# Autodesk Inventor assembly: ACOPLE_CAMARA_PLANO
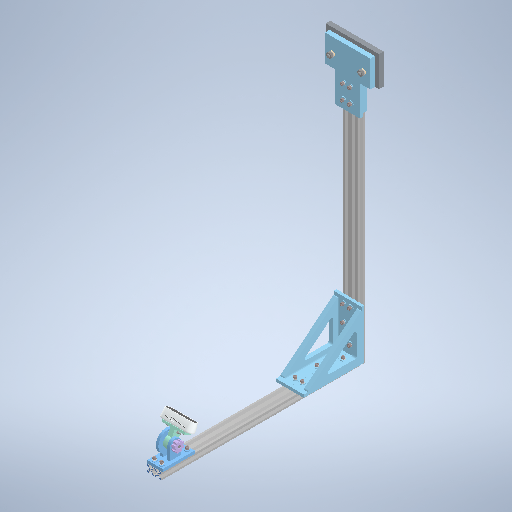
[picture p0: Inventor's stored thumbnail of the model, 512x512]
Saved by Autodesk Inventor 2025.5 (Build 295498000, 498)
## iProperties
Company: Open CASCADE
Created: 2026-10
Part Number: ACOPLE_CAMARA_PLANO
Description: Open CASCADE Model
Document SubType Name: Assembly
Designer: Luis M
Authority: Unknown
Sending System: Open CASCADE 7.9
Preprocessor: Open CASCADE STEP processor 7.9
Title: Open CASCADE Shape Model
Author: Author
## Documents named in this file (26)
- C:\Users\Luis M\Desktop\TESIS\CAD_TESIS\ACOPLE_CAMARA\ACOPLE_CAMARA_PLANO.iam
- C:\Users\Luis M\Desktop\TESIS\CAD_TESIS\ACOPLE_CAMARA\BOM_PLANO\IPT\ACAM-P02.ipt
- C:\Users\Luis M\Desktop\TESIS\CAD_TESIS\ACOPLE_CAMARA\BOM_PLANO\IPT\ACAM-P03.ipt
- C:\Users\Luis M\Desktop\TESIS\CAD_TESIS\ACOPLE_CAMARA\BOM_PLANO\IPT\ACAM-REF01.ipt
- C:\Users\Luis M\Desktop\TESIS\CAD_TESIS\ACOPLE_CAMARA\BOM_PLANO\IPT\ACAM-P08_izq.ipt
- C:\Users\Luis M\Desktop\TESIS\CAD_TESIS\ACOPLE_CAMARA\BOM_PLANO\IPT\ACAM-P08_der.ipt
- C:\Users\Luis M\Desktop\TESIS\CAD_TESIS\ACOPLE_CAMARA\BOM_PLANO\IPT\ACAM-C15.ipt
- C:\Users\Luis M\Desktop\TESIS\CAD_TESIS\ACOPLE_CAMARA\BOM_PLANO\IPT\ACAM-C01.ipt
- C:\Users\Luis M\Desktop\TESIS\CAD_TESIS\ACOPLE_CAMARA\BOM_PLANO\IPT\ACAM-C02.ipt
- C:\Users\Luis M\Desktop\TESIS\CAD_TESIS\ACOPLE_CAMARA\BOM_PLANO\IPT\ACAM-C03.ipt
- C:\Users\Luis M\Desktop\TESIS\CAD_TESIS\ACOPLE_CAMARA\BOM_PLANO\IPT\ACAM-C06.ipt
- C:\Users\Luis M\Desktop\TESIS\CAD_TESIS\ACOPLE_CAMARA\BOM_PLANO\IPT\ACAM-C04.ipt
- C:\Users\Luis M\Desktop\TESIS\CAD_TESIS\ACOPLE_CAMARA\BOM_PLANO\IPT\ACAM-C08.ipt
- C:\Users\Luis M\Desktop\TESIS\CAD_TESIS\ACOPLE_CAMARA\BOM_PLANO\IPT\ACAM-C09.ipt
- C:\Users\Luis M\Desktop\TESIS\CAD_TESIS\ACOPLE_CAMARA\BOM_PLANO\IPT\ACAM-C05.ipt
- C:\Users\Luis M\Desktop\TESIS\CAD_TESIS\ACOPLE_CAMARA\BOM_PLANO\IPT\ACAM-C07.ipt
- C:\Users\Luis M\Desktop\TESIS\CAD_TESIS\ACOPLE_CAMARA\BOM_PLANO\IPT\ACAM-C10.ipt
- C:\Users\Luis M\Desktop\TESIS\CAD_TESIS\ACOPLE_CAMARA\BOM_PLANO\IPT\ACAM-C11.ipt
- C:\Users\Luis M\Desktop\TESIS\CAD_TESIS\ACOPLE_CAMARA\BOM_PLANO\IPT\ACAM-C12.ipt
- C:\Users\Luis M\Desktop\TESIS\CAD_TESIS\ACOPLE_CAMARA\BOM_PLANO\IPT\ACAM-C13.ipt
- C:\Users\Luis M\Desktop\TESIS\CAD_TESIS\ACOPLE_CAMARA\BOM_PLANO\IPT\ACAM-C14.ipt
- C:\Users\Luis M\Desktop\TESIS\CAD_TESIS\ACOPLE_CAMARA\BOM_PLANO\IPT\ACAM-P01.ipt
- C:\Users\Luis M\Desktop\TESIS\CAD_TESIS\ACOPLE_CAMARA\BOM_PLANO\IPT\ACAM-P04.ipt
- C:\Users\Luis M\Desktop\TESIS\CAD_TESIS\ACOPLE_CAMARA\BOM_PLANO\IPT\ACAM-P05.ipt
- C:\Users\Luis M\Desktop\TESIS\CAD_TESIS\ACOPLE_CAMARA\BOM_PLANO\IPT\ACAM-P06.ipt
- C:\Users\Luis M\Desktop\TESIS\CAD_TESIS\ACOPLE_CAMARA\BOM_PLANO\IPT\ACAM-P07.ipt
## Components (94 placed, 24 different names)
1. ACAM-C01 Perfil V-Slot 2040 × 700:1 — Coincidencia:26, Nivelación:1, Nivelación:2, Coincidencia:36, Coincidencia:37, Coincidencia:38, Coincidencia:47, UF_01_Plano_1, UF_01_Plano_2, UF_01_Plano_3, UF_02_Plano_1, UF_02_Plano_2, UF_02_Plano_3, UF_03_Plano_1, UF_03_Plano_2, UF_03_Plano_3, UF_04_Plano_1, UF_04_Plano_2, UF_04_Plano_3, UF_05_Plano_1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
2. ACAM-C02 Perfil V-Slot 2040 × 550:1 — Coincidencia:26, Nivelación:1, Nivelación:2, Coincidencia:27, Coincidencia:28, Coincidencia:29, Coincidencia:46
3. ACAM-P01 Horquilla de cámara:1 — CM_01_Plano_1, CM_01_Plano_2, CM_01_Plano_3
4. ACAM-P02 Placa portacámara:1 — CM_02_Plano_1, CM_02_Plano_2, CM_02_Plano_3
5. ACAM-P03 Pomo de ajuste M5:1 — CM_03_Plano_1, CM_03_Plano_2, CM_03_Plano_3
6. ACAM-P04 Adaptador Jaco2–2040:1 — UF_01_Plano_1, UF_01_Plano_2, UF_01_Plano_3
7. ACAM-REF01 Base Jaco2 — referencia:1 — UF_02_Plano_1, UF_02_Plano_2, UF_02_Plano_3
8. ACAM-C03 Tornillo Allen M5×40:1 — CM_04_Plano_1, CM_04_Plano_2, CM_04_Plano_3
9. ACAM-C06 Arandela de presión M5 — DIN 127 B:1 — CM_05_Plano_1, CM_05_Plano_2, CM_05_Plano_3
10. ACAM-C06 Arandela de presión M5 — DIN 127 B:2 — CM_06_Plano_1, CM_06_Plano_2, CM_06_Plano_3
11. ACAM-C04 Tuerca hexagonal M5:1 — CM_07_Plano_1, CM_07_Plano_2, CM_07_Plano_3
12. ACAM-C08 Tornillo Allen M3×8:1 — CM_08_Plano_1, CM_08_Plano_2, CM_08_Plano_3
13. ACAM-C09 Arandela de presión M3 — DIN 127 B:1 — CM_09_Plano_1, CM_09_Plano_2, CM_09_Plano_3
14. ACAM-C08 Tornillo Allen M3×8:2 — CM_10_Plano_1, CM_10_Plano_2, CM_10_Plano_3
15. ACAM-C09 Arandela de presión M3 — DIN 127 B:2 — CM_11_Plano_1, CM_11_Plano_2, CM_11_Plano_3
16. ACAM-C05 Tornillo Allen M5×16:1 — CM_12_Plano_1, CM_12_Plano_2, CM_12_Plano_3
17. ACAM-C06 Arandela de presión M5 — DIN 127 B:3 — CM_13_Plano_1, CM_13_Plano_2, CM_13_Plano_3
18. ACAM-C07 Tuerca T M5 — modelo 2020:1 — CM_14_Plano_1, CM_14_Plano_2, CM_14_Plano_3
19. ACAM-C05 Tornillo Allen M5×16:2 — CM_15_Plano_1, CM_15_Plano_2, CM_15_Plano_3
20. ACAM-C06 Arandela de presión M5 — DIN 127 B:4 — CM_16_Plano_1, CM_16_Plano_2, CM_16_Plano_3
21. ACAM-C07 Tuerca T M5 — modelo 2020:2 — CM_17_Plano_1, CM_17_Plano_2, CM_17_Plano_3
22. ACAM-C05 Tornillo Allen M5×16:3 — UF_03_Plano_1, UF_03_Plano_2, UF_03_Plano_3
23. ACAM-C06 Arandela de presión M5 — DIN 127 B:5 — UF_04_Plano_1, UF_04_Plano_2, UF_04_Plano_3
24. ACAM-C07 Tuerca T M5 — modelo 2020:3 — UF_05_Plano_1, UF_05_Plano_2, UF_05_Plano_3
25. ACAM-C05 Tornillo Allen M5×16:4 — UF_06_Plano_1, UF_06_Plano_2, UF_06_Plano_3
26. ACAM-C06 Arandela de presión M5 — DIN 127 B:6 — UF_07_Plano_1, UF_07_Plano_2, UF_07_Plano_3
27. ACAM-C07 Tuerca T M5 — modelo 2020:4 — UF_08_Plano_1, UF_08_Plano_2, UF_08_Plano_3
28. ACAM-C05 Tornillo Allen M5×16:5 — CM_18_Plano_1, CM_18_Plano_2, CM_18_Plano_3
29. ACAM-C06 Arandela de presión M5 — DIN 127 B:7 — CM_19_Plano_1, CM_19_Plano_2, CM_19_Plano_3
30. ACAM-C07 Tuerca T M5 — modelo 2020:5 — CM_20_Plano_1, CM_20_Plano_2, CM_20_Plano_3
31. ACAM-C05 Tornillo Allen M5×16:6 — CM_21_Plano_1, CM_21_Plano_2, CM_21_Plano_3
32. ACAM-C06 Arandela de presión M5 — DIN 127 B:8 — CM_22_Plano_1, CM_22_Plano_2, CM_22_Plano_3
33. ACAM-C07 Tuerca T M5 — modelo 2020:6 — CM_23_Plano_1, CM_23_Plano_2, CM_23_Plano_3
34. ACAM-C05 Tornillo Allen M5×16:7 — UF_09_Plano_1, UF_09_Plano_2, UF_09_Plano_3
35. ACAM-C06 Arandela de presión M5 — DIN 127 B:9 — UF_10_Plano_1, UF_10_Plano_2, UF_10_Plano_3
36. ACAM-C07 Tuerca T M5 — modelo 2020:7 — UF_11_Plano_1, UF_11_Plano_2, UF_11_Plano_3
37. ACAM-C05 Tornillo Allen M5×16:8 — UF_12_Plano_1, UF_12_Plano_2, UF_12_Plano_3
38. ACAM-C06 Arandela de presión M5 — DIN 127 B:10 — UF_13_Plano_1, UF_13_Plano_2, UF_13_Plano_3
39. ACAM-C07 Tuerca T M5 — modelo 2020:8 — UF_14_Plano_1, UF_14_Plano_2, UF_14_Plano_3
40. ACAM-P05 Cartabón derecho:1
41. ACAM-P06 Cartabón izquierdo:1
42. ACAM-C05 Tornillo Allen M5×16:9 — Coincidencia:6, Coincidencia:12, Coincidencia:31, Coincidencia:54
43. ACAM-C06 Arandela de presión M5 — DIN 127 B:11 — Coincidencia:6, Coincidencia:12, Nivelación:23, Nivelación:25
44. ACAM-C07 Tuerca T M5 — modelo 2020:9 — Nivelación:3, Nivelación:8, Coincidencia:33
45. ACAM-C05 Tornillo Allen M5×16:10 — Coincidencia:4, Coincidencia:10, Coincidencia:34, Coincidencia:49
46. ACAM-C06 Arandela de presión M5 — DIN 127 B:12 — Coincidencia:4, Coincidencia:10, Nivelación:25, Nivelación:26, Coincidencia:48
47. ACAM-C07 Tuerca T M5 — modelo 2020:10 — Nivelación:5, Nivelación:6, Nivelación:10, Coincidencia:32
48. ACAM-C05 Tornillo Allen M5×16:11 — Coincidencia:3, Coincidencia:8, Coincidencia:35, Coincidencia:51
49. ACAM-C06 Arandela de presión M5 — DIN 127 B:13 — Coincidencia:3, Coincidencia:8, Nivelación:23, Nivelación:24
50. ACAM-C07 Tuerca T M5 — modelo 2020:11 — Nivelación:7, Nivelación:9, Coincidencia:34
51. ACAM-C05 Tornillo Allen M5×16:12 — Coincidencia:15, Coincidencia:25, Coincidencia:39, Coincidencia:56
52. ACAM-C06 Arandela de presión M5 — DIN 127 B:14 — Coincidencia:15, Coincidencia:25, Nivelación:31
53. ACAM-C07 Tuerca T M5 — modelo 2020:12 — Nivelación:12, Ángulo:5, Nivelación:17, Coincidencia:38, Coincidencia:40
54. ACAM-C05 Tornillo Allen M5×16:13 — Coincidencia:17, Coincidencia:23, Coincidencia:42, Coincidencia:60
55. ACAM-C06 Arandela de presión M5 — DIN 127 B:15 — Coincidencia:17, Coincidencia:23, Nivelación:28, Nivelación:29, Nivelación:32
56. ACAM-C07 Tuerca T M5 — modelo 2020:13 — Nivelación:16, Ángulo:4, Ángulo:5, Nivelación:17, Nivelación:18, Coincidencia:42
57. ACAM-C05 Tornillo Allen M5×16:14 — Coincidencia:19, Coincidencia:21, Coincidencia:44
58. ACAM-C06 Arandela de presión M5 — DIN 127 B:16 — Coincidencia:19, Coincidencia:21, Nivelación:28
59. ACAM-C07 Tuerca T M5 — modelo 2020:14 — Nivelación:15, Nivelación:16, Ángulo:3, Ángulo:4, Nivelación:18, Coincidencia:44, Coincidencia:59
60. ACAM-C05 Tornillo Allen M5×16:15 — Coincidencia:7, Coincidencia:13, Coincidencia:32, Coincidencia:53
61. ACAM-C06 Arandela de presión M5 — DIN 127 B:17 — Coincidencia:7, Coincidencia:13, Nivelación:26, Nivelación:27
62. ACAM-C07 Tuerca T M5 — modelo 2020:15 — Nivelación:3, Nivelación:4, Nivelación:8, Nivelación:9, Coincidencia:29, Coincidencia:35
63. ACAM-C05 Tornillo Allen M5×16:16 — Coincidencia:5, Coincidencia:11, Coincidencia:33, Coincidencia:50
64. ACAM-C06 Arandela de presión M5 — DIN 127 B:18 — Coincidencia:5, Coincidencia:11, Nivelación:24
65. ACAM-C07 Tuerca T M5 — modelo 2020:16 — Nivelación:4, Nivelación:5, Nivelación:10, Coincidencia:31
66. ACAM-C05 Tornillo Allen M5×16:17 — Coincidencia:2, Coincidencia:9, Coincidencia:30, Coincidencia:52
67. ACAM-C06 Arandela de presión M5 — DIN 127 B:19 — Coincidencia:2, Coincidencia:9, Nivelación:27
68. ACAM-C07 Tuerca T M5 — modelo 2020:17 — Nivelación:6, Nivelación:7, Coincidencia:27, Coincidencia:28, Coincidencia:30
69. ACAM-C05 Tornillo Allen M5×16:18 — Coincidencia:14, Coincidencia:24, Coincidencia:40, Coincidencia:61
70. ACAM-C06 Arandela de presión M5 — DIN 127 B:20 — Coincidencia:14, Coincidencia:24, Nivelación:29
71. ACAM-C07 Tuerca T M5 — modelo 2020:18 — Nivelación:12, Nivelación:13, Ángulo:1, Nivelación:20, Coincidencia:36, Coincidencia:41
72. ACAM-C05 Tornillo Allen M5×16:19 — Coincidencia:16, Coincidencia:22, Coincidencia:41, Coincidencia:58
73. ACAM-C06 Arandela de presión M5 — DIN 127 B:21 — Coincidencia:16, Coincidencia:22, Nivelación:30, Nivelación:32, Coincidencia:55
74. ACAM-C07 Tuerca T M5 — modelo 2020:19
75. ACAM-C05 Tornillo Allen M5×16:20 — Coincidencia:18, Coincidencia:20, Coincidencia:43, Coincidencia:57
76. ACAM-C06 Arandela de presión M5 — DIN 127 B:22 — Coincidencia:18, Coincidencia:20, Nivelación:30, Nivelación:31
77. ACAM-C07 Tuerca T M5 — modelo 2020:20 — Nivelación:14, Nivelación:15, Ángulo:2, Ángulo:3, Nivelación:19, Coincidencia:43
78. ACAM-C10 Tornillo avellanado M8×40 — DIN 7991:1 — UF_15_Plano_1, UF_15_Plano_2, UF_15_Plano_3
79. ACAM-C11 Arandela de presión M8 — DIN 127 B:1 — UF_16_Plano_1, UF_16_Plano_2, UF_16_Plano_3
80. ACAM-C11 Arandela de presión M8 — DIN 127 B:2 — UF_17_Plano_1, UF_17_Plano_2, UF_17_Plano_3
81. ACAM-P07 Casquillo M8:1 — UF_18_Plano_1, UF_18_Plano_2, UF_18_Plano_3
82. ACAM-P08 Centrador Ø15–M8:1 — UF_19_Plano_1, UF_19_Plano_2, UF_19_Plano_3
83. ACAM-C12 Tuerca hexagonal M8:1 — UF_20_Plano_1, UF_20_Plano_2, UF_20_Plano_3
84. ACAM-C10 Tornillo avellanado M8×40 — DIN 7991:2 — UF_21_Plano_1, UF_21_Plano_2, UF_21_Plano_3
85. ACAM-C11 Arandela de presión M8 — DIN 127 B:3 — UF_22_Plano_1, UF_22_Plano_2, UF_22_Plano_3
86. ACAM-C11 Arandela de presión M8 — DIN 127 B:4 — UF_23_Plano_1, UF_23_Plano_2, UF_23_Plano_3
87. ACAM-P07 Casquillo M8:2 — UF_24_Plano_1, UF_24_Plano_2, UF_24_Plano_3
88. ACAM-P08 Centrador Ø15–M8:2 — UF_25_Plano_1, UF_25_Plano_2, UF_25_Plano_3
89. ACAM-C12 Tuerca hexagonal M8:2 — UF_26_Plano_1, UF_26_Plano_2, UF_26_Plano_3
90. ACAM-C13 Tornillo Allen M3×30:1 — CM_24_Plano_1, CM_24_Plano_2, CM_24_Plano_3
91. ACAM-C09 Arandela de presión M3 — DIN 127 B:3 — CM_25_Plano_1, CM_25_Plano_2, CM_25_Plano_3
92. ACAM-C09 Arandela de presión M3 — DIN 127 B:4 — CM_26_Plano_1, CM_26_Plano_2, CM_26_Plano_3
93. ACAM-C14 Tuerca hexagonal M3:1 — CM_27_Plano_1, CM_27_Plano_2, CM_27_Plano_3
94. ACAM-C15 Cámara Intel RealSense D435i:1 — CM_28_Plano_1, CM_28_Plano_2, CM_28_Plano_3
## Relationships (255: Flush 139, Mate 111, Angle 5)
- Coincidencia:2 [Mate]: ACAM-C05 Tornillo Allen M5×16:17 ↔ ACAM-C06 Arandela de presión M5 — DIN 127 B:19
- Coincidencia:3 [Mate]: ACAM-C05 Tornillo Allen M5×16:11 ↔ ACAM-C06 Arandela de presión M5 — DIN 127 B:13
- Coincidencia:4 [Mate]: ACAM-C05 Tornillo Allen M5×16:10 ↔ ACAM-C06 Arandela de presión M5 — DIN 127 B:12
- Coincidencia:5 [Mate]: ACAM-C05 Tornillo Allen M5×16:16 ↔ ACAM-C06 Arandela de presión M5 — DIN 127 B:18
- Coincidencia:6 [Mate]: ACAM-C05 Tornillo Allen M5×16:9 ↔ ACAM-C06 Arandela de presión M5 — DIN 127 B:11
- Coincidencia:7 [Mate]: ACAM-C05 Tornillo Allen M5×16:15 ↔ ACAM-C06 Arandela de presión M5 — DIN 127 B:17
- Coincidencia:8 [Mate]: ACAM-C05 Tornillo Allen M5×16:11 ↔ ACAM-C06 Arandela de presión M5 — DIN 127 B:13
- Coincidencia:9 [Mate]: ACAM-C05 Tornillo Allen M5×16:17 ↔ ACAM-C06 Arandela de presión M5 — DIN 127 B:19
- Coincidencia:10 [Mate]: ACAM-C05 Tornillo Allen M5×16:10 ↔ ACAM-C06 Arandela de presión M5 — DIN 127 B:12
- Coincidencia:11 [Mate]: ACAM-C05 Tornillo Allen M5×16:16 ↔ ACAM-C06 Arandela de presión M5 — DIN 127 B:18
- Coincidencia:12 [Mate]: ACAM-C05 Tornillo Allen M5×16:9 ↔ ACAM-C06 Arandela de presión M5 — DIN 127 B:11
- Coincidencia:13 [Mate]: ACAM-C05 Tornillo Allen M5×16:15 ↔ ACAM-C06 Arandela de presión M5 — DIN 127 B:17
- Coincidencia:14 [Mate]: ACAM-C05 Tornillo Allen M5×16:18 ↔ ACAM-C06 Arandela de presión M5 — DIN 127 B:20
- Coincidencia:15 [Mate]: ACAM-C05 Tornillo Allen M5×16:12 ↔ ACAM-C06 Arandela de presión M5 — DIN 127 B:14
- Coincidencia:16 [Mate]: ACAM-C05 Tornillo Allen M5×16:19 ↔ ACAM-C06 Arandela de presión M5 — DIN 127 B:21
- Coincidencia:17 [Mate]: ACAM-C05 Tornillo Allen M5×16:13 ↔ ACAM-C06 Arandela de presión M5 — DIN 127 B:15
- Coincidencia:18 [Mate]: ACAM-C05 Tornillo Allen M5×16:20 ↔ ACAM-C06 Arandela de presión M5 — DIN 127 B:22
- Coincidencia:19 [Mate]: ACAM-C05 Tornillo Allen M5×16:14 ↔ ACAM-C06 Arandela de presión M5 — DIN 127 B:16
- Coincidencia:20 [Mate]: ACAM-C05 Tornillo Allen M5×16:20 ↔ ACAM-C06 Arandela de presión M5 — DIN 127 B:22
- Coincidencia:21 [Mate]: ACAM-C05 Tornillo Allen M5×16:14 ↔ ACAM-C06 Arandela de presión M5 — DIN 127 B:16
- Coincidencia:22 [Mate]: ACAM-C05 Tornillo Allen M5×16:19 ↔ ACAM-C06 Arandela de presión M5 — DIN 127 B:21
- Coincidencia:23 [Mate]: ACAM-C05 Tornillo Allen M5×16:13 ↔ ACAM-C06 Arandela de presión M5 — DIN 127 B:15
- Coincidencia:24 [Mate]: ACAM-C05 Tornillo Allen M5×16:18 ↔ ACAM-C06 Arandela de presión M5 — DIN 127 B:20
- Coincidencia:25 [Mate]: ACAM-C05 Tornillo Allen M5×16:12 ↔ ACAM-C06 Arandela de presión M5 — DIN 127 B:14
- Coincidencia:26 [Mate]: ACAM-C01 Perfil V-Slot 2040 × 700:1 ↔ ACAM-C02 Perfil V-Slot 2040 × 550:1
- Nivelación:1 [Flush]: ACAM-C01 Perfil V-Slot 2040 × 700:1 ↔ ACAM-C02 Perfil V-Slot 2040 × 550:1
- Nivelación:2 [Flush]: ACAM-C01 Perfil V-Slot 2040 × 700:1 ↔ ACAM-C02 Perfil V-Slot 2040 × 550:1
- Nivelación:3 [Flush]: ACAM-C07 Tuerca T M5 — modelo 2020:9 ↔ ACAM-C07 Tuerca T M5 — modelo 2020:15
- Nivelación:4 [Flush]: ACAM-C07 Tuerca T M5 — modelo 2020:15 ↔ ACAM-C07 Tuerca T M5 — modelo 2020:16
- Nivelación:5 [Flush]: ACAM-C07 Tuerca T M5 — modelo 2020:10 ↔ ACAM-C07 Tuerca T M5 — modelo 2020:16
- Nivelación:6 [Flush]: ACAM-C07 Tuerca T M5 — modelo 2020:10 ↔ ACAM-C07 Tuerca T M5 — modelo 2020:17
- Nivelación:7 [Flush]: ACAM-C07 Tuerca T M5 — modelo 2020:11 ↔ ACAM-C07 Tuerca T M5 — modelo 2020:17
- Coincidencia:27 [Mate]: ACAM-C02 Perfil V-Slot 2040 × 550:1 ↔ ACAM-C07 Tuerca T M5 — modelo 2020:17
- Nivelación:8 [Flush]: ACAM-C07 Tuerca T M5 — modelo 2020:9 ↔ ACAM-C07 Tuerca T M5 — modelo 2020:15
- Nivelación:9 [Flush]: ACAM-C07 Tuerca T M5 — modelo 2020:11 ↔ ACAM-C07 Tuerca T M5 — modelo 2020:15
- Nivelación:10 [Flush]: ACAM-C07 Tuerca T M5 — modelo 2020:10 ↔ ACAM-C07 Tuerca T M5 — modelo 2020:16
- Coincidencia:28 [Mate]: ACAM-C02 Perfil V-Slot 2040 × 550:1 ↔ ACAM-C07 Tuerca T M5 — modelo 2020:17
- Coincidencia:29 [Mate]: ACAM-C02 Perfil V-Slot 2040 × 550:1 ↔ ACAM-C07 Tuerca T M5 — modelo 2020:15
- Coincidencia:30 [Mate]: ACAM-C05 Tornillo Allen M5×16:17 ↔ ACAM-C07 Tuerca T M5 — modelo 2020:17
- Coincidencia:31 [Mate]: ACAM-C05 Tornillo Allen M5×16:9 ↔ ACAM-C07 Tuerca T M5 — modelo 2020:16
- Coincidencia:32 [Mate]: ACAM-C07 Tuerca T M5 — modelo 2020:10 ↔ ACAM-C05 Tornillo Allen M5×16:15
- Coincidencia:33 [Mate]: ACAM-C07 Tuerca T M5 — modelo 2020:9 ↔ ACAM-C05 Tornillo Allen M5×16:16
- Coincidencia:34 [Mate]: ACAM-C05 Tornillo Allen M5×16:10 ↔ ACAM-C07 Tuerca T M5 — modelo 2020:11
- Coincidencia:35 [Mate]: ACAM-C05 Tornillo Allen M5×16:11 ↔ ACAM-C07 Tuerca T M5 — modelo 2020:15
- Nivelación:12 [Flush]: ACAM-C07 Tuerca T M5 — modelo 2020:12 ↔ ACAM-C07 Tuerca T M5 — modelo 2020:18
- Nivelación:13 [Flush]: ACAM-C07 Tuerca T M5 — modelo 2020:18
- Nivelación:14 [Flush]: ACAM-C07 Tuerca T M5 — modelo 2020:20
- Nivelación:15 [Flush]: ACAM-C07 Tuerca T M5 — modelo 2020:14 ↔ ACAM-C07 Tuerca T M5 — modelo 2020:20
- Nivelación:16 [Flush]: ACAM-C07 Tuerca T M5 — modelo 2020:13 ↔ ACAM-C07 Tuerca T M5 — modelo 2020:14
- Ángulo:1 [Angle]: ACAM-C07 Tuerca T M5 — modelo 2020:18
- Ángulo:2 [Angle]: ACAM-C07 Tuerca T M5 — modelo 2020:20
- Ángulo:3 [Angle]: ACAM-C07 Tuerca T M5 — modelo 2020:14 ↔ ACAM-C07 Tuerca T M5 — modelo 2020:20
- Ángulo:4 [Angle]: ACAM-C07 Tuerca T M5 — modelo 2020:13 ↔ ACAM-C07 Tuerca T M5 — modelo 2020:14
- Ángulo:5 [Angle]: ACAM-C07 Tuerca T M5 — modelo 2020:12 ↔ ACAM-C07 Tuerca T M5 — modelo 2020:13
- Nivelación:17 [Flush]: ACAM-C07 Tuerca T M5 — modelo 2020:12 ↔ ACAM-C07 Tuerca T M5 — modelo 2020:13
- Nivelación:18 [Flush]: ACAM-C07 Tuerca T M5 — modelo 2020:13 ↔ ACAM-C07 Tuerca T M5 — modelo 2020:14
- Nivelación:19 [Flush]: ACAM-C07 Tuerca T M5 — modelo 2020:20
- Nivelación:20 [Flush]: ACAM-C07 Tuerca T M5 — modelo 2020:18
- Coincidencia:36 [Mate]: ACAM-C01 Perfil V-Slot 2040 × 700:1 ↔ ACAM-C07 Tuerca T M5 — modelo 2020:18
- Coincidencia:37 [Mate]: ACAM-C01 Perfil V-Slot 2040 × 700:1
- Coincidencia:38 [Mate]: ACAM-C01 Perfil V-Slot 2040 × 700:1 ↔ ACAM-C07 Tuerca T M5 — modelo 2020:12
- Coincidencia:39 [Mate]: ACAM-C05 Tornillo Allen M5×16:12
- Coincidencia:40 [Mate]: ACAM-C07 Tuerca T M5 — modelo 2020:12 ↔ ACAM-C05 Tornillo Allen M5×16:18
- Coincidencia:41 [Mate]: ACAM-C07 Tuerca T M5 — modelo 2020:18 ↔ ACAM-C05 Tornillo Allen M5×16:19
- Coincidencia:42 [Mate]: ACAM-C05 Tornillo Allen M5×16:13 ↔ ACAM-C07 Tuerca T M5 — modelo 2020:13
- Coincidencia:43 [Mate]: ACAM-C05 Tornillo Allen M5×16:20 ↔ ACAM-C07 Tuerca T M5 — modelo 2020:20
- Coincidencia:44 [Mate]: ACAM-C05 Tornillo Allen M5×16:14 ↔ ACAM-C07 Tuerca T M5 — modelo 2020:14
- Coincidencia:46 [Mate]: ACAM-C02 Perfil V-Slot 2040 × 550:1
- Coincidencia:47 [Mate]: ACAM-C01 Perfil V-Slot 2040 × 700:1
- Nivelación:23 [Flush]: ACAM-C06 Arandela de presión M5 — DIN 127 B:11 ↔ ACAM-C06 Arandela de presión M5 — DIN 127 B:13
- Nivelación:24 [Flush]: ACAM-C06 Arandela de presión M5 — DIN 127 B:13 ↔ ACAM-C06 Arandela de presión M5 — DIN 127 B:18
- Nivelación:25 [Flush]: ACAM-C06 Arandela de presión M5 — DIN 127 B:11 ↔ ACAM-C06 Arandela de presión M5 — DIN 127 B:12
- Nivelación:26 [Flush]: ACAM-C06 Arandela de presión M5 — DIN 127 B:12 ↔ ACAM-C06 Arandela de presión M5 — DIN 127 B:17
- Nivelación:27 [Flush]: ACAM-C06 Arandela de presión M5 — DIN 127 B:17 ↔ ACAM-C06 Arandela de presión M5 — DIN 127 B:19
- Coincidencia:48 [Mate]: ACAM-C06 Arandela de presión M5 — DIN 127 B:12
- Coincidencia:49 [Mate]: ACAM-C05 Tornillo Allen M5×16:10
- Coincidencia:50 [Mate]: ACAM-C05 Tornillo Allen M5×16:16
- Coincidencia:51 [Mate]: ACAM-C05 Tornillo Allen M5×16:11
- Coincidencia:52 [Mate]: ACAM-C05 Tornillo Allen M5×16:17
- Coincidencia:53 [Mate]: ACAM-C05 Tornillo Allen M5×16:15
- Coincidencia:54 [Mate]: ACAM-C05 Tornillo Allen M5×16:9
- Nivelación:28 [Flush]: ACAM-C06 Arandela de presión M5 — DIN 127 B:15 ↔ ACAM-C06 Arandela de presión M5 — DIN 127 B:16
- Nivelación:29 [Flush]: ACAM-C06 Arandela de presión M5 — DIN 127 B:15 ↔ ACAM-C06 Arandela de presión M5 — DIN 127 B:20
- Nivelación:30 [Flush]: ACAM-C06 Arandela de presión M5 — DIN 127 B:21 ↔ ACAM-C06 Arandela de presión M5 — DIN 127 B:22
- Nivelación:31 [Flush]: ACAM-C06 Arandela de presión M5 — DIN 127 B:14 ↔ ACAM-C06 Arandela de presión M5 — DIN 127 B:22
- Nivelación:32 [Flush]: ACAM-C06 Arandela de presión M5 — DIN 127 B:15 ↔ ACAM-C06 Arandela de presión M5 — DIN 127 B:21
- Coincidencia:55 [Mate]: ACAM-C06 Arandela de presión M5 — DIN 127 B:21
- Coincidencia:56 [Mate]: ACAM-C05 Tornillo Allen M5×16:12
- Coincidencia:57 [Mate]: ACAM-C05 Tornillo Allen M5×16:20
- Coincidencia:58 [Mate]: ACAM-C05 Tornillo Allen M5×16:19
- Coincidencia:59 [Mate]: ACAM-C07 Tuerca T M5 — modelo 2020:14
- Coincidencia:60 [Mate]: ACAM-C05 Tornillo Allen M5×16:13
- Coincidencia:61 [Mate]: ACAM-C05 Tornillo Allen M5×16:18
- UF_01_Plano_1 [Flush]: ACAM-C01 Perfil V-Slot 2040 × 700:1 ↔ ACAM-P04 Adaptador Jaco2–2040:1
- UF_01_Plano_2 [Mate]: ACAM-C01 Perfil V-Slot 2040 × 700:1 ↔ ACAM-P04 Adaptador Jaco2–2040:1
- UF_01_Plano_3 [Flush]: ACAM-C01 Perfil V-Slot 2040 × 700:1 ↔ ACAM-P04 Adaptador Jaco2–2040:1
- UF_02_Plano_1 [Flush]: ACAM-C01 Perfil V-Slot 2040 × 700:1 ↔ ACAM-REF01 Base Jaco2 — referencia:1
- UF_02_Plano_2 [Mate]: ACAM-C01 Perfil V-Slot 2040 × 700:1 ↔ ACAM-REF01 Base Jaco2 — referencia:1
- UF_02_Plano_3 [Flush]: ACAM-C01 Perfil V-Slot 2040 × 700:1 ↔ ACAM-REF01 Base Jaco2 — referencia:1
- UF_03_Plano_1 [Mate]: ACAM-C01 Perfil V-Slot 2040 × 700:1 ↔ ACAM-C05 Tornillo Allen M5×16:3
- UF_03_Plano_2 [Flush]: ACAM-C01 Perfil V-Slot 2040 × 700:1 ↔ ACAM-C05 Tornillo Allen M5×16:3
- UF_03_Plano_3 [Flush]: ACAM-C01 Perfil V-Slot 2040 × 700:1 ↔ ACAM-C05 Tornillo Allen M5×16:3
- UF_04_Plano_1 [Flush]: ACAM-C01 Perfil V-Slot 2040 × 700:1 ↔ ACAM-C06 Arandela de presión M5 — DIN 127 B:5
- UF_04_Plano_2 [Mate]: ACAM-C01 Perfil V-Slot 2040 × 700:1 ↔ ACAM-C06 Arandela de presión M5 — DIN 127 B:5
- UF_04_Plano_3 [Flush]: ACAM-C01 Perfil V-Slot 2040 × 700:1 ↔ ACAM-C06 Arandela de presión M5 — DIN 127 B:5
- UF_05_Plano_1 [Flush]: ACAM-C01 Perfil V-Slot 2040 × 700:1 ↔ ACAM-C07 Tuerca T M5 — modelo 2020:3
- UF_05_Plano_2 [Flush]: ACAM-C01 Perfil V-Slot 2040 × 700:1 ↔ ACAM-C07 Tuerca T M5 — modelo 2020:3
- UF_05_Plano_3 [Flush]: ACAM-C01 Perfil V-Slot 2040 × 700:1 ↔ ACAM-C07 Tuerca T M5 — modelo 2020:3
- UF_06_Plano_1 [Mate]: ACAM-C01 Perfil V-Slot 2040 × 700:1 ↔ ACAM-C05 Tornillo Allen M5×16:4
- UF_06_Plano_2 [Flush]: ACAM-C01 Perfil V-Slot 2040 × 700:1 ↔ ACAM-C05 Tornillo Allen M5×16:4
- UF_06_Plano_3 [Flush]: ACAM-C01 Perfil V-Slot 2040 × 700:1 ↔ ACAM-C05 Tornillo Allen M5×16:4
- UF_07_Plano_1 [Flush]: ACAM-C01 Perfil V-Slot 2040 × 700:1 ↔ ACAM-C06 Arandela de presión M5 — DIN 127 B:6
- UF_07_Plano_2 [Mate]: ACAM-C01 Perfil V-Slot 2040 × 700:1 ↔ ACAM-C06 Arandela de presión M5 — DIN 127 B:6
- UF_07_Plano_3 [Flush]: ACAM-C01 Perfil V-Slot 2040 × 700:1 ↔ ACAM-C06 Arandela de presión M5 — DIN 127 B:6
- UF_08_Plano_1 [Flush]: ACAM-C01 Perfil V-Slot 2040 × 700:1 ↔ ACAM-C07 Tuerca T M5 — modelo 2020:4
- UF_08_Plano_2 [Flush]: ACAM-C01 Perfil V-Slot 2040 × 700:1 ↔ ACAM-C07 Tuerca T M5 — modelo 2020:4
- UF_08_Plano_3 [Flush]: ACAM-C01 Perfil V-Slot 2040 × 700:1 ↔ ACAM-C07 Tuerca T M5 — modelo 2020:4
- UF_09_Plano_1 [Mate]: ACAM-C01 Perfil V-Slot 2040 × 700:1 ↔ ACAM-C05 Tornillo Allen M5×16:7
- UF_09_Plano_2 [Flush]: ACAM-C01 Perfil V-Slot 2040 × 700:1 ↔ ACAM-C05 Tornillo Allen M5×16:7
- UF_09_Plano_3 [Flush]: ACAM-C01 Perfil V-Slot 2040 × 700:1 ↔ ACAM-C05 Tornillo Allen M5×16:7
- UF_10_Plano_1 [Flush]: ACAM-C01 Perfil V-Slot 2040 × 700:1 ↔ ACAM-C06 Arandela de presión M5 — DIN 127 B:9
- UF_10_Plano_2 [Mate]: ACAM-C01 Perfil V-Slot 2040 × 700:1 ↔ ACAM-C06 Arandela de presión M5 — DIN 127 B:9
- UF_10_Plano_3 [Flush]: ACAM-C01 Perfil V-Slot 2040 × 700:1 ↔ ACAM-C06 Arandela de presión M5 — DIN 127 B:9
- UF_11_Plano_1 [Flush]: ACAM-C01 Perfil V-Slot 2040 × 700:1 ↔ ACAM-C07 Tuerca T M5 — modelo 2020:7
- UF_11_Plano_2 [Flush]: ACAM-C01 Perfil V-Slot 2040 × 700:1 ↔ ACAM-C07 Tuerca T M5 — modelo 2020:7
- UF_11_Plano_3 [Flush]: ACAM-C01 Perfil V-Slot 2040 × 700:1 ↔ ACAM-C07 Tuerca T M5 — modelo 2020:7
- UF_12_Plano_1 [Mate]: ACAM-C01 Perfil V-Slot 2040 × 700:1 ↔ ACAM-C05 Tornillo Allen M5×16:8
- UF_12_Plano_2 [Flush]: ACAM-C01 Perfil V-Slot 2040 × 700:1 ↔ ACAM-C05 Tornillo Allen M5×16:8
- UF_12_Plano_3 [Flush]: ACAM-C01 Perfil V-Slot 2040 × 700:1 ↔ ACAM-C05 Tornillo Allen M5×16:8
- UF_13_Plano_1 [Flush]: ACAM-C01 Perfil V-Slot 2040 × 700:1 ↔ ACAM-C06 Arandela de presión M5 — DIN 127 B:10
- UF_13_Plano_2 [Mate]: ACAM-C01 Perfil V-Slot 2040 × 700:1 ↔ ACAM-C06 Arandela de presión M5 — DIN 127 B:10
- UF_13_Plano_3 [Flush]: ACAM-C01 Perfil V-Slot 2040 × 700:1 ↔ ACAM-C06 Arandela de presión M5 — DIN 127 B:10
- UF_14_Plano_1 [Flush]: ACAM-C01 Perfil V-Slot 2040 × 700:1 ↔ ACAM-C07 Tuerca T M5 — modelo 2020:8
- UF_14_Plano_2 [Flush]: ACAM-C01 Perfil V-Slot 2040 × 700:1 ↔ ACAM-C07 Tuerca T M5 — modelo 2020:8
- UF_14_Plano_3 [Flush]: ACAM-C01 Perfil V-Slot 2040 × 700:1 ↔ ACAM-C07 Tuerca T M5 — modelo 2020:8
- UF_15_Plano_1 [Flush]: ACAM-C01 Perfil V-Slot 2040 × 700:1 ↔ ACAM-C10 Tornillo avellanado M8×40 — DIN 7991:1
- UF_15_Plano_2 [Flush]: ACAM-C01 Perfil V-Slot 2040 × 700:1 ↔ ACAM-C10 Tornillo avellanado M8×40 — DIN 7991:1
- UF_15_Plano_3 [Mate]: ACAM-C01 Perfil V-Slot 2040 × 700:1 ↔ ACAM-C10 Tornillo avellanado M8×40 — DIN 7991:1
- UF_16_Plano_1 [Flush]: ACAM-C01 Perfil V-Slot 2040 × 700:1 ↔ ACAM-C11 Arandela de presión M8 — DIN 127 B:1
- UF_16_Plano_2 [Mate]: ACAM-C01 Perfil V-Slot 2040 × 700:1 ↔ ACAM-C11 Arandela de presión M8 — DIN 127 B:1
- UF_16_Plano_3 [Flush]: ACAM-C01 Perfil V-Slot 2040 × 700:1 ↔ ACAM-C11 Arandela de presión M8 — DIN 127 B:1
- UF_17_Plano_1 [Flush]: ACAM-C01 Perfil V-Slot 2040 × 700:1 ↔ ACAM-C11 Arandela de presión M8 — DIN 127 B:2
- UF_17_Plano_2 [Mate]: ACAM-C01 Perfil V-Slot 2040 × 700:1 ↔ ACAM-C11 Arandela de presión M8 — DIN 127 B:2
- UF_17_Plano_3 [Flush]: ACAM-C01 Perfil V-Slot 2040 × 700:1 ↔ ACAM-C11 Arandela de presión M8 — DIN 127 B:2
- UF_18_Plano_1 [Flush]: ACAM-C01 Perfil V-Slot 2040 × 700:1 ↔ ACAM-P07 Casquillo M8:1
- UF_18_Plano_2 [Mate]: ACAM-C01 Perfil V-Slot 2040 × 700:1 ↔ ACAM-P07 Casquillo M8:1
- UF_18_Plano_3 [Flush]: ACAM-C01 Perfil V-Slot 2040 × 700:1 ↔ ACAM-P07 Casquillo M8:1
- UF_19_Plano_1 [Flush]: ACAM-C01 Perfil V-Slot 2040 × 700:1 ↔ ACAM-P08 Centrador Ø15–M8:1
- UF_19_Plano_2 [Mate]: ACAM-C01 Perfil V-Slot 2040 × 700:1 ↔ ACAM-P08 Centrador Ø15–M8:1
- UF_19_Plano_3 [Flush]: ACAM-C01 Perfil V-Slot 2040 × 700:1 ↔ ACAM-P08 Centrador Ø15–M8:1
- UF_20_Plano_1 [Flush]: ACAM-C01 Perfil V-Slot 2040 × 700:1 ↔ ACAM-C12 Tuerca hexagonal M8:1
- UF_20_Plano_2 [Mate]: ACAM-C01 Perfil V-Slot 2040 × 700:1 ↔ ACAM-C12 Tuerca hexagonal M8:1
- UF_20_Plano_3 [Flush]: ACAM-C01 Perfil V-Slot 2040 × 700:1 ↔ ACAM-C12 Tuerca hexagonal M8:1
- UF_21_Plano_1 [Flush]: ACAM-C01 Perfil V-Slot 2040 × 700:1 ↔ ACAM-C10 Tornillo avellanado M8×40 — DIN 7991:2
- UF_21_Plano_2 [Flush]: ACAM-C01 Perfil V-Slot 2040 × 700:1 ↔ ACAM-C10 Tornillo avellanado M8×40 — DIN 7991:2
- UF_21_Plano_3 [Mate]: ACAM-C01 Perfil V-Slot 2040 × 700:1 ↔ ACAM-C10 Tornillo avellanado M8×40 — DIN 7991:2
- UF_22_Plano_1 [Flush]: ACAM-C01 Perfil V-Slot 2040 × 700:1 ↔ ACAM-C11 Arandela de presión M8 — DIN 127 B:3
- UF_22_Plano_2 [Mate]: ACAM-C01 Perfil V-Slot 2040 × 700:1 ↔ ACAM-C11 Arandela de presión M8 — DIN 127 B:3
- UF_22_Plano_3 [Flush]: ACAM-C01 Perfil V-Slot 2040 × 700:1 ↔ ACAM-C11 Arandela de presión M8 — DIN 127 B:3
- UF_23_Plano_1 [Flush]: ACAM-C01 Perfil V-Slot 2040 × 700:1 ↔ ACAM-C11 Arandela de presión M8 — DIN 127 B:4
- UF_23_Plano_2 [Mate]: ACAM-C01 Perfil V-Slot 2040 × 700:1 ↔ ACAM-C11 Arandela de presión M8 — DIN 127 B:4
- UF_23_Plano_3 [Flush]: ACAM-C01 Perfil V-Slot 2040 × 700:1 ↔ ACAM-C11 Arandela de presión M8 — DIN 127 B:4
- UF_24_Plano_1 [Flush]: ACAM-C01 Perfil V-Slot 2040 × 700:1 ↔ ACAM-P07 Casquillo M8:2
- UF_24_Plano_2 [Mate]: ACAM-C01 Perfil V-Slot 2040 × 700:1 ↔ ACAM-P07 Casquillo M8:2
- UF_24_Plano_3 [Flush]: ACAM-C01 Perfil V-Slot 2040 × 700:1 ↔ ACAM-P07 Casquillo M8:2
- UF_25_Plano_1 [Flush]: ACAM-C01 Perfil V-Slot 2040 × 700:1 ↔ ACAM-P08 Centrador Ø15–M8:2
- UF_25_Plano_2 [Mate]: ACAM-C01 Perfil V-Slot 2040 × 700:1 ↔ ACAM-P08 Centrador Ø15–M8:2
- UF_25_Plano_3 [Flush]: ACAM-C01 Perfil V-Slot 2040 × 700:1 ↔ ACAM-P08 Centrador Ø15–M8:2
- UF_26_Plano_1 [Flush]: ACAM-C01 Perfil V-Slot 2040 × 700:1 ↔ ACAM-C12 Tuerca hexagonal M8:2
- UF_26_Plano_2 [Mate]: ACAM-C01 Perfil V-Slot 2040 × 700:1 ↔ ACAM-C12 Tuerca hexagonal M8:2
- UF_26_Plano_3 [Flush]: ACAM-C01 Perfil V-Slot 2040 × 700:1 ↔ ACAM-C12 Tuerca hexagonal M8:2
- CM_01_Plano_1 [Flush]: ACAM-C01 Perfil V-Slot 2040 × 700:1 ↔ ACAM-P01 Horquilla de cámara:1
- CM_01_Plano_2 [Mate]: ACAM-C01 Perfil V-Slot 2040 × 700:1 ↔ ACAM-P01 Horquilla de cámara:1
- CM_01_Plano_3 [Flush]: ACAM-C01 Perfil V-Slot 2040 × 700:1 ↔ ACAM-P01 Horquilla de cámara:1
- CM_02_Plano_1 [Flush]: ACAM-C01 Perfil V-Slot 2040 × 700:1 ↔ ACAM-P02 Placa portacámara:1
- CM_02_Plano_2 [Mate]: ACAM-C01 Perfil V-Slot 2040 × 700:1 ↔ ACAM-P02 Placa portacámara:1
- CM_02_Plano_3 [Flush]: ACAM-C01 Perfil V-Slot 2040 × 700:1 ↔ ACAM-P02 Placa portacámara:1
- CM_03_Plano_1 [Flush]: ACAM-C01 Perfil V-Slot 2040 × 700:1 ↔ ACAM-P03 Pomo de ajuste M5:1
- CM_03_Plano_2 [Mate]: ACAM-C01 Perfil V-Slot 2040 × 700:1 ↔ ACAM-P03 Pomo de ajuste M5:1
- CM_03_Plano_3 [Flush]: ACAM-C01 Perfil V-Slot 2040 × 700:1 ↔ ACAM-P03 Pomo de ajuste M5:1
- CM_04_Plano_1 [Flush]: ACAM-C01 Perfil V-Slot 2040 × 700:1 ↔ ACAM-C03 Tornillo Allen M5×40:1
- CM_04_Plano_2 [Mate]: ACAM-C01 Perfil V-Slot 2040 × 700:1 ↔ ACAM-C03 Tornillo Allen M5×40:1
- CM_04_Plano_3 [Flush]: ACAM-C01 Perfil V-Slot 2040 × 700:1 ↔ ACAM-C03 Tornillo Allen M5×40:1
- CM_05_Plano_1 [Mate]: ACAM-C01 Perfil V-Slot 2040 × 700:1 ↔ ACAM-C06 Arandela de presión M5 — DIN 127 B:1
- CM_05_Plano_2 [Flush]: ACAM-C01 Perfil V-Slot 2040 × 700:1 ↔ ACAM-C06 Arandela de presión M5 — DIN 127 B:1
- CM_05_Plano_3 [Flush]: ACAM-C01 Perfil V-Slot 2040 × 700:1 ↔ ACAM-C06 Arandela de presión M5 — DIN 127 B:1
- CM_06_Plano_1 [Mate]: ACAM-C01 Perfil V-Slot 2040 × 700:1 ↔ ACAM-C06 Arandela de presión M5 — DIN 127 B:2
- CM_06_Plano_2 [Flush]: ACAM-C01 Perfil V-Slot 2040 × 700:1 ↔ ACAM-C06 Arandela de presión M5 — DIN 127 B:2
- CM_06_Plano_3 [Flush]: ACAM-C01 Perfil V-Slot 2040 × 700:1 ↔ ACAM-C06 Arandela de presión M5 — DIN 127 B:2
- CM_07_Plano_1 [Mate]: ACAM-C01 Perfil V-Slot 2040 × 700:1 ↔ ACAM-C04 Tuerca hexagonal M5:1
- CM_07_Plano_2 [Flush]: ACAM-C01 Perfil V-Slot 2040 × 700:1 ↔ ACAM-C04 Tuerca hexagonal M5:1
- CM_07_Plano_3 [Flush]: ACAM-C01 Perfil V-Slot 2040 × 700:1 ↔ ACAM-C04 Tuerca hexagonal M5:1
- CM_08_Plano_1 [Flush]: ACAM-C01 Perfil V-Slot 2040 × 700:1 ↔ ACAM-C08 Tornillo Allen M3×8:1
- CM_08_Plano_2 [Flush]: ACAM-C08 Tornillo Allen M3×8:1
- CM_08_Plano_3 [Flush]: ACAM-C08 Tornillo Allen M3×8:1
- CM_09_Plano_1 [Flush]: ACAM-C01 Perfil V-Slot 2040 × 700:1 ↔ ACAM-C09 Arandela de presión M3 — DIN 127 B:1
- CM_09_Plano_2 [Mate]: ACAM-C09 Arandela de presión M3 — DIN 127 B:1
- CM_09_Plano_3 [Mate]: ACAM-C09 Arandela de presión M3 — DIN 127 B:1
- CM_10_Plano_1 [Flush]: ACAM-C01 Perfil V-Slot 2040 × 700:1 ↔ ACAM-C08 Tornillo Allen M3×8:2
- CM_10_Plano_2 [Flush]: ACAM-C08 Tornillo Allen M3×8:2
- CM_10_Plano_3 [Flush]: ACAM-C08 Tornillo Allen M3×8:2
- CM_11_Plano_1 [Flush]: ACAM-C01 Perfil V-Slot 2040 × 700:1 ↔ ACAM-C09 Arandela de presión M3 — DIN 127 B:2
- CM_11_Plano_2 [Mate]: ACAM-C09 Arandela de presión M3 — DIN 127 B:2
- CM_11_Plano_3 [Mate]: ACAM-C09 Arandela de presión M3 — DIN 127 B:2
- CM_12_Plano_1 [Flush]: ACAM-C01 Perfil V-Slot 2040 × 700:1 ↔ ACAM-C05 Tornillo Allen M5×16:1
- CM_12_Plano_2 [Flush]: ACAM-C01 Perfil V-Slot 2040 × 700:1 ↔ ACAM-C05 Tornillo Allen M5×16:1
- CM_12_Plano_3 [Flush]: ACAM-C01 Perfil V-Slot 2040 × 700:1 ↔ ACAM-C05 Tornillo Allen M5×16:1
- CM_13_Plano_1 [Flush]: ACAM-C01 Perfil V-Slot 2040 × 700:1 ↔ ACAM-C06 Arandela de presión M5 — DIN 127 B:3
- CM_13_Plano_2 [Mate]: ACAM-C01 Perfil V-Slot 2040 × 700:1 ↔ ACAM-C06 Arandela de presión M5 — DIN 127 B:3
- CM_13_Plano_3 [Mate]: ACAM-C01 Perfil V-Slot 2040 × 700:1 ↔ ACAM-C06 Arandela de presión M5 — DIN 127 B:3
- CM_14_Plano_1 [Flush]: ACAM-C01 Perfil V-Slot 2040 × 700:1 ↔ ACAM-C07 Tuerca T M5 — modelo 2020:1
- CM_14_Plano_2 [Mate]: ACAM-C01 Perfil V-Slot 2040 × 700:1 ↔ ACAM-C07 Tuerca T M5 — modelo 2020:1
- CM_14_Plano_3 [Flush]: ACAM-C01 Perfil V-Slot 2040 × 700:1 ↔ ACAM-C07 Tuerca T M5 — modelo 2020:1
- CM_15_Plano_1 [Flush]: ACAM-C01 Perfil V-Slot 2040 × 700:1 ↔ ACAM-C05 Tornillo Allen M5×16:2
- CM_15_Plano_2 [Flush]: ACAM-C01 Perfil V-Slot 2040 × 700:1 ↔ ACAM-C05 Tornillo Allen M5×16:2
- CM_15_Plano_3 [Flush]: ACAM-C01 Perfil V-Slot 2040 × 700:1 ↔ ACAM-C05 Tornillo Allen M5×16:2
- CM_16_Plano_1 [Flush]: ACAM-C01 Perfil V-Slot 2040 × 700:1 ↔ ACAM-C06 Arandela de presión M5 — DIN 127 B:4
- CM_16_Plano_2 [Mate]: ACAM-C01 Perfil V-Slot 2040 × 700:1 ↔ ACAM-C06 Arandela de presión M5 — DIN 127 B:4
- CM_16_Plano_3 [Mate]: ACAM-C01 Perfil V-Slot 2040 × 700:1 ↔ ACAM-C06 Arandela de presión M5 — DIN 127 B:4
- CM_17_Plano_1 [Flush]: ACAM-C01 Perfil V-Slot 2040 × 700:1 ↔ ACAM-C07 Tuerca T M5 — modelo 2020:2
- CM_17_Plano_2 [Mate]: ACAM-C01 Perfil V-Slot 2040 × 700:1 ↔ ACAM-C07 Tuerca T M5 — modelo 2020:2
- CM_17_Plano_3 [Flush]: ACAM-C01 Perfil V-Slot 2040 × 700:1 ↔ ACAM-C07 Tuerca T M5 — modelo 2020:2
- CM_18_Plano_1 [Flush]: ACAM-C01 Perfil V-Slot 2040 × 700:1 ↔ ACAM-C05 Tornillo Allen M5×16:5
- CM_18_Plano_2 [Flush]: ACAM-C01 Perfil V-Slot 2040 × 700:1 ↔ ACAM-C05 Tornillo Allen M5×16:5
- CM_18_Plano_3 [Flush]: ACAM-C01 Perfil V-Slot 2040 × 700:1 ↔ ACAM-C05 Tornillo Allen M5×16:5
- CM_19_Plano_1 [Flush]: ACAM-C01 Perfil V-Slot 2040 × 700:1 ↔ ACAM-C06 Arandela de presión M5 — DIN 127 B:7
- CM_19_Plano_2 [Mate]: ACAM-C01 Perfil V-Slot 2040 × 700:1 ↔ ACAM-C06 Arandela de presión M5 — DIN 127 B:7
- CM_19_Plano_3 [Mate]: ACAM-C01 Perfil V-Slot 2040 × 700:1 ↔ ACAM-C06 Arandela de presión M5 — DIN 127 B:7
- CM_20_Plano_1 [Flush]: ACAM-C01 Perfil V-Slot 2040 × 700:1 ↔ ACAM-C07 Tuerca T M5 — modelo 2020:5
- CM_20_Plano_2 [Mate]: ACAM-C01 Perfil V-Slot 2040 × 700:1 ↔ ACAM-C07 Tuerca T M5 — modelo 2020:5
- CM_20_Plano_3 [Flush]: ACAM-C01 Perfil V-Slot 2040 × 700:1 ↔ ACAM-C07 Tuerca T M5 — modelo 2020:5
- CM_21_Plano_1 [Flush]: ACAM-C01 Perfil V-Slot 2040 × 700:1 ↔ ACAM-C05 Tornillo Allen M5×16:6
- CM_21_Plano_2 [Flush]: ACAM-C01 Perfil V-Slot 2040 × 700:1 ↔ ACAM-C05 Tornillo Allen M5×16:6
- CM_21_Plano_3 [Flush]: ACAM-C01 Perfil V-Slot 2040 × 700:1 ↔ ACAM-C05 Tornillo Allen M5×16:6
- CM_22_Plano_1 [Flush]: ACAM-C01 Perfil V-Slot 2040 × 700:1 ↔ ACAM-C06 Arandela de presión M5 — DIN 127 B:8
- CM_22_Plano_2 [Mate]: ACAM-C01 Perfil V-Slot 2040 × 700:1 ↔ ACAM-C06 Arandela de presión M5 — DIN 127 B:8
- CM_22_Plano_3 [Mate]: ACAM-C01 Perfil V-Slot 2040 × 700:1 ↔ ACAM-C06 Arandela de presión M5 — DIN 127 B:8
- CM_23_Plano_1 [Flush]: ACAM-C01 Perfil V-Slot 2040 × 700:1 ↔ ACAM-C07 Tuerca T M5 — modelo 2020:6
- CM_23_Plano_2 [Mate]: ACAM-C01 Perfil V-Slot 2040 × 700:1 ↔ ACAM-C07 Tuerca T M5 — modelo 2020:6
- CM_23_Plano_3 [Flush]: ACAM-C01 Perfil V-Slot 2040 × 700:1 ↔ ACAM-C07 Tuerca T M5 — modelo 2020:6
- CM_24_Plano_1 [Mate]: ACAM-C01 Perfil V-Slot 2040 × 700:1 ↔ ACAM-C13 Tornillo Allen M3×30:1
- CM_24_Plano_2 [Mate]: ACAM-C01 Perfil V-Slot 2040 × 700:1 ↔ ACAM-C13 Tornillo Allen M3×30:1
- CM_24_Plano_3 [Mate]: ACAM-C01 Perfil V-Slot 2040 × 700:1 ↔ ACAM-C13 Tornillo Allen M3×30:1
- CM_25_Plano_1 [Mate]: ACAM-C01 Perfil V-Slot 2040 × 700:1 ↔ ACAM-C09 Arandela de presión M3 — DIN 127 B:3
- CM_25_Plano_2 [Flush]: ACAM-C01 Perfil V-Slot 2040 × 700:1 ↔ ACAM-C09 Arandela de presión M3 — DIN 127 B:3
- CM_25_Plano_3 [Flush]: ACAM-C01 Perfil V-Slot 2040 × 700:1 ↔ ACAM-C09 Arandela de presión M3 — DIN 127 B:3
- CM_26_Plano_1 [Mate]: ACAM-C01 Perfil V-Slot 2040 × 700:1 ↔ ACAM-C09 Arandela de presión M3 — DIN 127 B:4
- CM_26_Plano_2 [Flush]: ACAM-C01 Perfil V-Slot 2040 × 700:1 ↔ ACAM-C09 Arandela de presión M3 — DIN 127 B:4
- CM_26_Plano_3 [Flush]: ACAM-C01 Perfil V-Slot 2040 × 700:1 ↔ ACAM-C09 Arandela de presión M3 — DIN 127 B:4
- CM_27_Plano_1 [Mate]: ACAM-C01 Perfil V-Slot 2040 × 700:1 ↔ ACAM-C14 Tuerca hexagonal M3:1
- CM_27_Plano_2 [Flush]: ACAM-C01 Perfil V-Slot 2040 × 700:1 ↔ ACAM-C14 Tuerca hexagonal M3:1
- CM_27_Plano_3 [Flush]: ACAM-C01 Perfil V-Slot 2040 × 700:1 ↔ ACAM-C14 Tuerca hexagonal M3:1
- CM_28_Plano_1 [Flush]: ACAM-C01 Perfil V-Slot 2040 × 700:1 ↔ ACAM-C15 Cámara Intel RealSense D435i:1
- CM_28_Plano_2 [Mate]: ACAM-C15 Cámara Intel RealSense D435i:1
- CM_28_Plano_3 [Flush]: ACAM-C15 Cámara Intel RealSense D435i:1
